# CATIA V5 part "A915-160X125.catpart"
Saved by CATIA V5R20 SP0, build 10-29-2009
Part number: A915-160X125
Source: Unknown
Property "A": "110.000"
Property "ARTICLENO": "A915-160X125"
Property "BOMINFO": "A915-160X125"
Property "CODE": "A915-160X125"
Property "CREATOR": "CADENAS GmbH"
Property "D": "13.500"
Property "D1": "20.000"
Property "FORM": "C"
Property "L": "125.000"
Property "L1": "25.000"
Property "L2": "75.000"
Property "LINA": "A915-160X125"
Property "NB": "A915-160X125"
Property "NBSYN": "$CODE."
Property "NN": "A915"
Property "NT": "VDI 3357 Wear Plates, steel"
Property "SCREW": "M12x25"
Property "SUPPLIER": "CF"
Property "T": "13.000"
Property "W": "160.000"
Bounding box of the stored display mesh (mm): x 0 to 20, y 0 to 125, z -80 to 80
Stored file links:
  C:\Users\borellobunino\Desktop\3D X SITO CF\A915\GSB_OILLESS_G22501160125\CATIAV5\A915-160X125.catpart
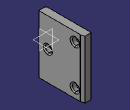
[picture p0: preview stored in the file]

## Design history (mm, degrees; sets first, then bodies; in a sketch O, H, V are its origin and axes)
Body1 "Geometry.1" (main body)
  Solid1 "A915-160X125.catpart": solid without history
